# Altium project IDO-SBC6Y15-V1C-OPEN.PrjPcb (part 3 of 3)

## Sheet P12 EXPAND.SchDoc
size 594 x 420 mm
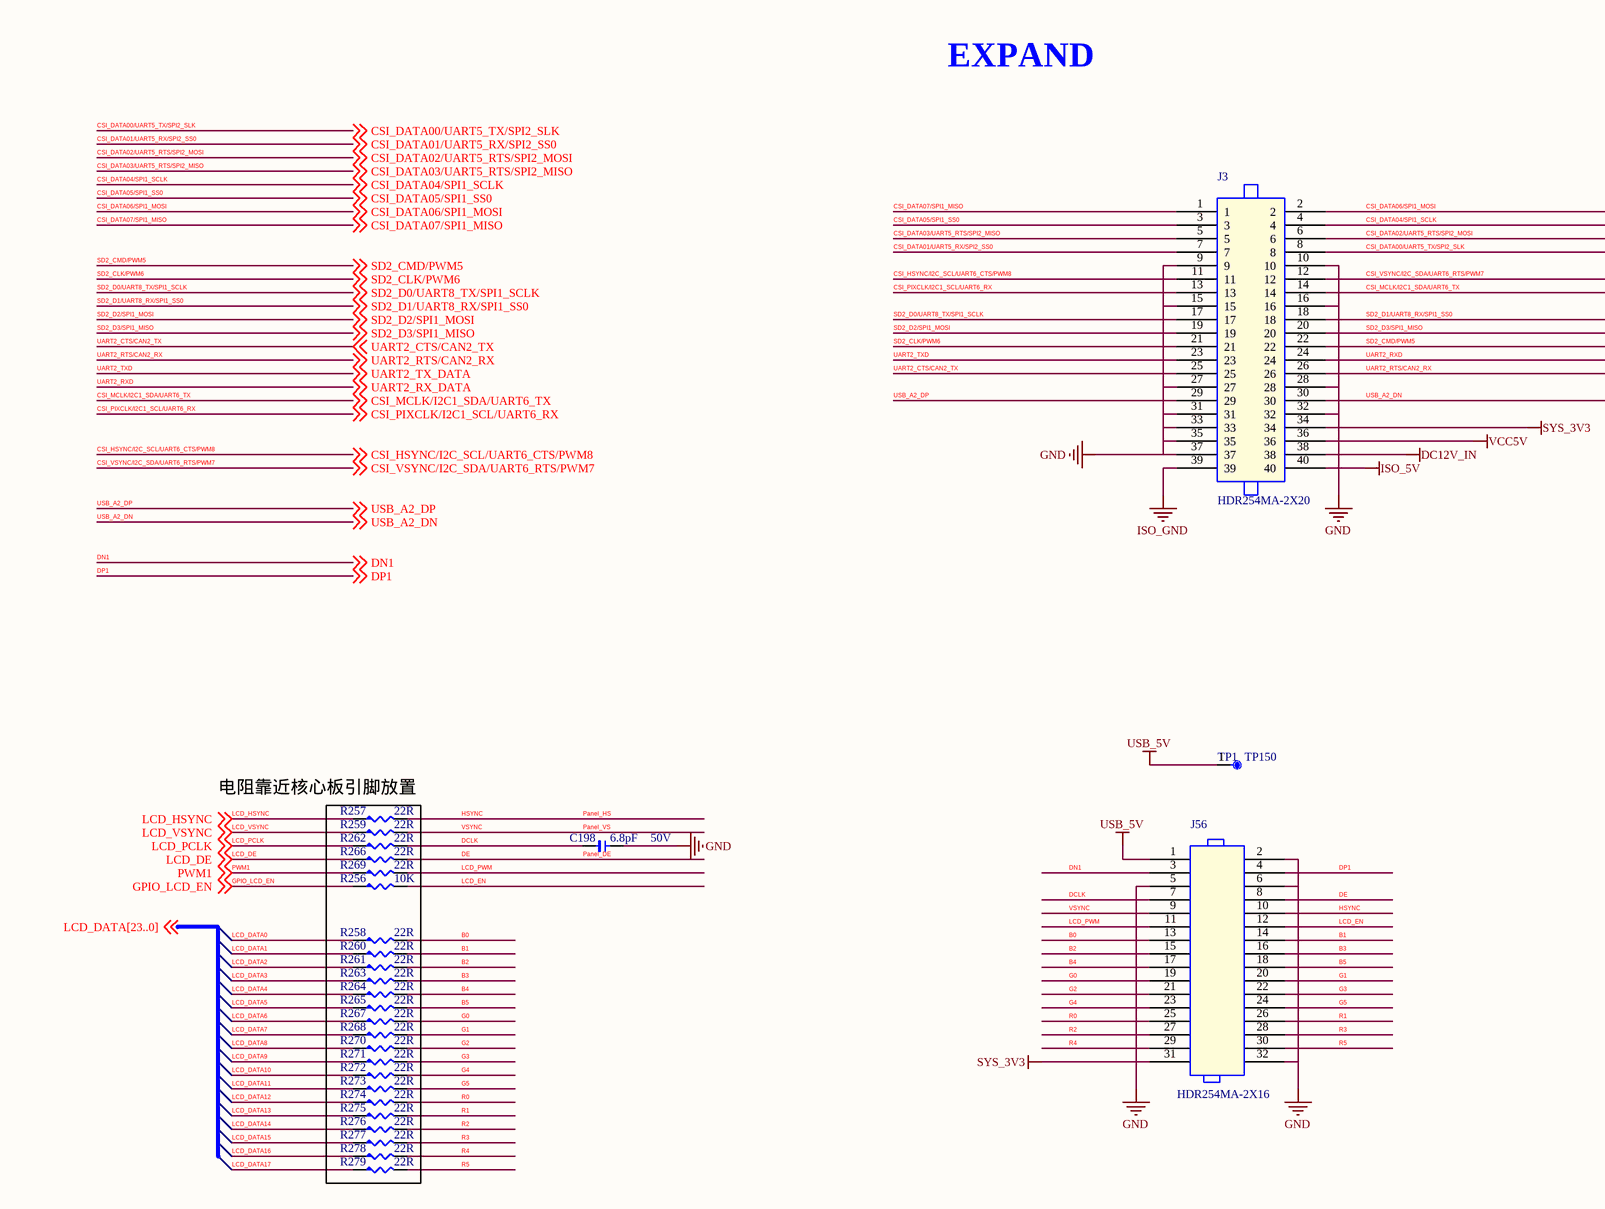
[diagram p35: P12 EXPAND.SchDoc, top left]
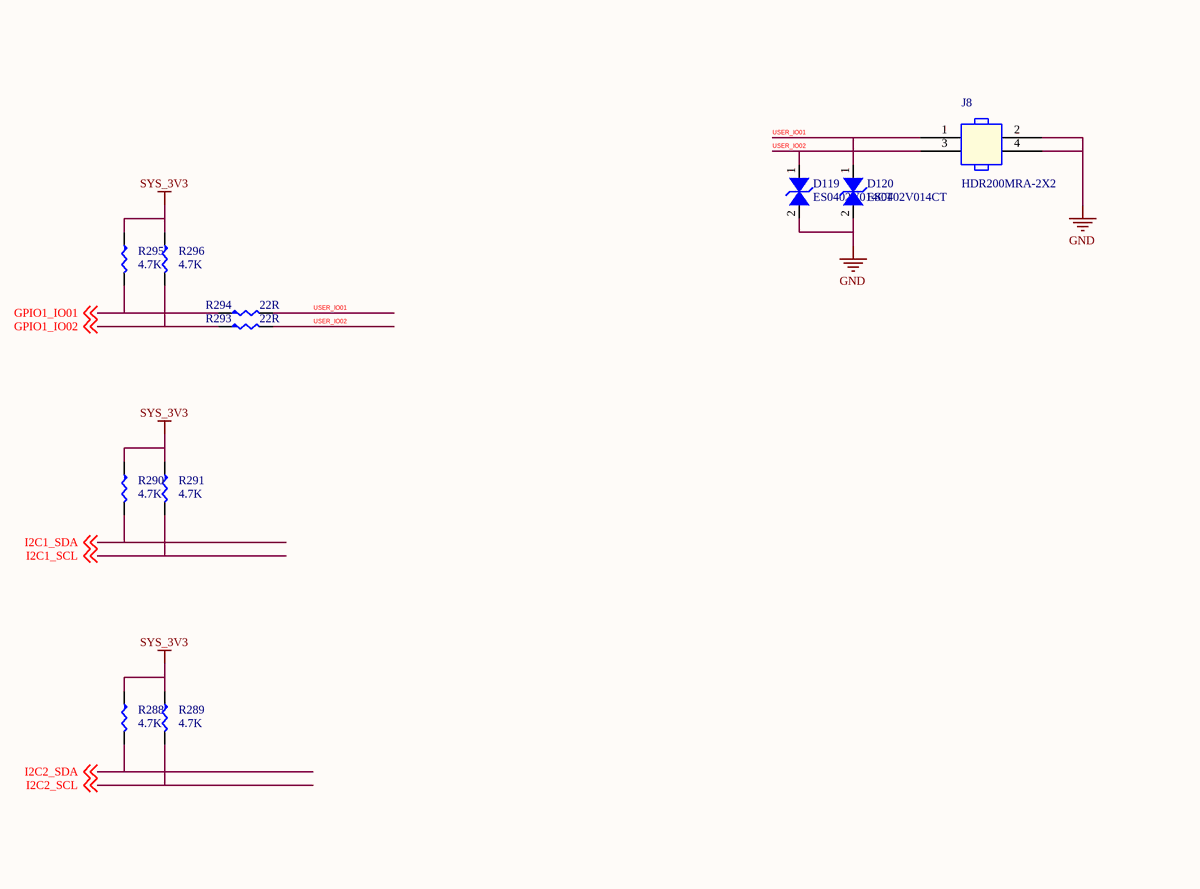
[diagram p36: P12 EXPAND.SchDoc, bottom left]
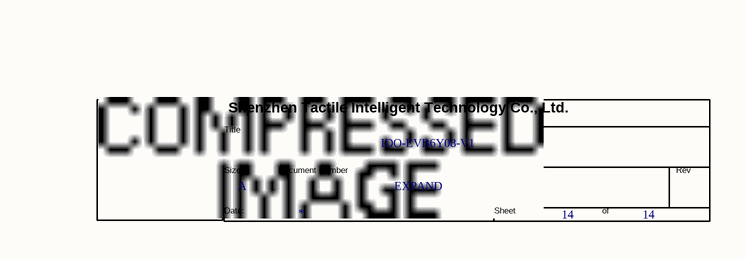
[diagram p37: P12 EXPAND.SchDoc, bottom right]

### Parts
(Parts that share a designator on the sheet are numbered #1, #2 ... from top to bottom, then left to right.)
*#11  Doc: EXPAND  Title: IDO-EVB6Y08-V1  Page Size: A  Page Number: 14  (hidden comment: TitleBlock1)  (graphical)
C198  6.8pF  DSC2: 50V  [1206]
D119  ES0402V014CT  [V0402]
D120  ES0402V014CT  [V0402]
J3  HDR254MA-2X20  [HDR254MA-2X20]
J8  HDR200MRA-2X2  [HDR200MRA-2X2]
J56  HDR254MA-2X16  [HDR254MA-2X16]
R256  10K  [R0402L]
R257  22R  [R0402L]
R258  22R  [R0402L]
R259  22R  [R0402L]
R260  22R  [R0402L]
R261  22R  [R0402L]
R262  22R  [R0402L]
R263  22R  [R0402L]
R264  22R  [R0402L]
R265  22R  [R0402L]
R266  22R  [R0402L]
R267  22R  [R0402L]
R268  22R  [R0402L]
R269  22R  [R0402L]
R270  22R  [R0402L]
R271  22R  [R0402L]
R272  22R  [R0402L]
R273  22R  [R0402L]
R274  22R  [R0402L]
R275  22R  [R0402L]
R276  22R  [R0402L]
R277  22R  [R0402L]
R278  22R  [R0402L]
R279  22R  [R0402L]
R288  4.7K  [R0402L]
R289  4.7K  [R0402L]
R290  4.7K  [R0402L]
R291  4.7K  [R0402L]
R293  22R  [R0402L]
R294  22R  [R0402L]
R295  4.7K  [R0402L]
R296  4.7K  [R0402L]
TP1  TP150  [smd_tp_1mm]

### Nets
DC12V_IN: J3.38
GND: C198.1 D119.2(I/O1) D120.2(I/O1) J3.9 J3.10 J3.15 J3.16 J3.27 J3.28 J3.31 J3.32 J3.33 J3.35 J3.37 J8.2 J8.4 J56.2 J56.5 J56.6 J56.32
ISO_5V: J3.40
ISO_GND: J3.39
SYS_3V3: J3.34 J56.31 R288.1 R289.1 R290.1 R291.1 R295.1 R296.1
USB_5V: J56.1 TP1.1
VCC5V: J3.36
B0: J56.13 R258.2
B1: J56.14 R260.2
B2: J56.15 R261.2
B3: J56.16 R263.2
B4: J56.17 R264.2
B5: J56.18 R265.2
CSI_DATA00/UART5_TX/SPI2_SLK: J3.8 ; off-sheet CSI_DATA00/UART5_TX/SPI2_SLK
CSI_DATA01/UART5_RX/SPI2_SS0: J3.7 ; off-sheet CSI_DATA01/UART5_RX/SPI2_SS0
CSI_DATA02/UART5_RTS/SPI2_MOSI: J3.6 ; off-sheet CSI_DATA02/UART5_RTS/SPI2_MOSI
CSI_DATA03/UART5_RTS/SPI2_MISO: J3.5 ; off-sheet CSI_DATA03/UART5_RTS/SPI2_MISO
CSI_DATA04/SPI1_SCLK: J3.4 ; off-sheet CSI_DATA04/SPI1_SCLK
CSI_DATA05/SPI1_SS0: J3.3 ; off-sheet CSI_DATA05/SPI1_SS0
CSI_DATA06/SPI1_MOSI: J3.2 ; off-sheet CSI_DATA06/SPI1_MOSI
CSI_DATA07/SPI1_MISO: J3.1 ; off-sheet CSI_DATA07/SPI1_MISO
CSI_HSYNC/I2C_SCL/UART6_CTS/PWM8: J3.11 ; off-sheet CSI_HSYNC/I2C_SCL/UART6_CTS/PWM8
CSI_MCLK/I2C1_SDA/UART6_TX: J3.14 ; off-sheet CSI_MCLK/I2C1_SDA/UART6_TX
CSI_PIXCLK/I2C1_SCL/UART6_RX: J3.13 ; off-sheet CSI_PIXCLK/I2C1_SCL/UART6_RX
CSI_VSYNC/I2C_SDA/UART6_RTS/PWM7: J3.12 ; off-sheet CSI_VSYNC/I2C_SDA/UART6_RTS/PWM7
DCLK: C198.2 J56.7 R262.2
DE: J56.8 R266.2  [also labelled Panel_DE]
DN1: J56.3 ; off-sheet DN1
DP1: J56.4 ; off-sheet DP1
G0: J56.19 R267.2
G1: J56.20 R268.2
G2: J56.21 R270.2
G3: J56.22 R271.2
G4: J56.23 R272.2
G5: J56.24 R273.2
GPIO1_IO01: R294.1 R295.2 ; off-sheet GPIO1_IO01
GPIO1_IO02: R293.1 R296.2 ; off-sheet GPIO1_IO02
GPIO_LCD_EN: R256.1 ; off-sheet GPIO_LCD_EN
HSYNC: J56.10 R257.2  [also labelled Panel_HS]
I2C1_SCL: R291.2 ; off-sheet I2C1_SCL  [project net CSI_PIXCLK]
I2C1_SDA: R290.2 ; off-sheet I2C1_SDA  [project net CSI_MCLK]
I2C2_SCL: R289.2 ; off-sheet I2C2_SCL  [project net CSI_HSYNC]
I2C2_SDA: R288.2 ; off-sheet I2C2_SDA  [project net CSI_VSYNC]
LCD_DATA0: R258.1
LCD_DATA1: R260.1
LCD_DATA2: R261.1
LCD_DATA3: R263.1
LCD_DATA4: R264.1
LCD_DATA5: R265.1
LCD_DATA6: R267.1
LCD_DATA7: R268.1
LCD_DATA8: R270.1
LCD_DATA9: R271.1
LCD_DATA10: R272.1
LCD_DATA11: R273.1
LCD_DATA12: R274.1
LCD_DATA13: R275.1
LCD_DATA14: R276.1
LCD_DATA15: R277.1
LCD_DATA16: R278.1
LCD_DATA17: R279.1
LCD_DE: R266.1 ; off-sheet LCD_DE
LCD_EN: J56.12 R256.2
LCD_HSYNC: R257.1 ; off-sheet LCD_HSYNC
LCD_PCLK: R262.1 ; off-sheet LCD_PCLK
LCD_PWM: J56.11 R269.2
LCD_VSYNC: R259.1 ; off-sheet LCD_VSYNC
Panel_VS: J56.9 R259.2  [also labelled VSYNC]
PWM1: R269.1 ; off-sheet PWM1  [project net GPIO1_IO08]
R0: J56.25 R274.2
R1: J56.26 R275.2
R2: J56.27 R276.2
R3: J56.28 R277.2
R4: J56.29 R278.2
R5: J56.30 R279.2
SD2_CLK/PWM6: J3.21 ; off-sheet SD2_CLK/PWM6
SD2_CMD/PWM5: J3.22 ; off-sheet SD2_CMD/PWM5
SD2_D0/UART8_TX/SPI1_SCLK: J3.17 ; off-sheet SD2_D0/UART8_TX/SPI1_SCLK
SD2_D1/UART8_RX/SPI1_SS0: J3.18 ; off-sheet SD2_D1/UART8_RX/SPI1_SS0
SD2_D2/SPI1_MOSI: J3.19 ; off-sheet SD2_D2/SPI1_MOSI
SD2_D3/SPI1_MISO: J3.20 ; off-sheet SD2_D3/SPI1_MISO
UART2_CTS/CAN2_TX: J3.25 ; off-sheet UART2_CTS/CAN2_TX
UART2_RTS/CAN2_RX: J3.26 ; off-sheet UART2_RTS/CAN2_RX
UART2_RX_DATA: J3.24 ; off-sheet UART2_RX_DATA  [also labelled UART2_RXD]
UART2_TX_DATA: J3.23 ; off-sheet UART2_TX_DATA  [also labelled UART2_TXD]
USB_A2_DN: J3.30 ; off-sheet USB_A2_DN
USB_A2_DP: J3.29 ; off-sheet USB_A2_DP
USER_IO01: D120.1(I/O2) J8.1 R294.2
USER_IO02: D119.1(I/O2) J8.3 R293.2

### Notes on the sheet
- EXPAND
- 电阻靠近核心板引脚放置

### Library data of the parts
C198 = C-0402: Part Number: C020102120018; Part Name: 贴片电容; Manufacture: 三星¦国巨¦村田; ERP Number: 1010200056; DSC1: ±0.25PF; DSC3: C0G; ID: 18; PCB Footprint: C0402L
D119 D120 = DI-ESD: ESD 0402; Part Number: C040502250002; Manufacture P/N: MLVG04021R0UV18; Manufacturer: INPAQ; Manufacture: AEM; PN Type: Varistor; ERP Number: 1010800023; DSC1: 双向; DSC2: Vdc=14V; DSC3: Vbr=300V; DSC4: Vc=30V; DSC5: Cj=0.25pF; ID: 2
J3 = J-HDR-D-40: Part Number: J010104013835; Part Name: 双排针; DSC1: 双排单塑; DSC2: 2x20; DSC3: 2.54mm脚距; DSC4: 通孔直针; DSC5: 针长11.5mm 3+2.5(H塑高)+6mm; DSC6: 黑胶; DSC7: A2541WV-2x20P(CJT); ID: 64
J8 = J-HDR-D-4: Part Name: 双排针; Part Number: J010102760077; ID: 21; DSC7: A2005WR-2x2P（CJT); DSC6: 黑胶; DSC5: 2.8+2(H塑高)+4 mm; DSC4: 通孔弯针; DSC3: 2mm脚距; DSC2: 2x2; DSC1: 双排单塑; ERP Number: 1040100150
J56 = J-HDR-D-30_1: Part Name: 双排针; Part Number: J010102760129; ID: 52; DSC7: A2541WV-2x16P(CJT); DSC6: 黑胶; DSC5: 针长11.5mm 3+2.5(H塑高)+6mm; DSC4: 通孔直针; DSC3: 2.54mm脚距; DSC2: 2x16; DSC1: 双排单塑
R256 = R-0402: Part Name: 贴片电阻; Part Number: C011002080856; ERP Number: 1010200140; DSC1: ±1%; DSC2: 1/16W; ID: 856
R257 R259 R262 R266 R269 = R-0402: Part Name: 贴片电阻; Part Number: C011002080552; DSC1: ±1%; DSC2: 1/16W; ID: 552
R258 R260 R261 R263-R265 R267 R268 R270-R279 R293 R294 = R-0402: Part Number: C011002080552; Part Name: 贴片电阻; ID: 552; DSC2: 1/16W; DSC1: ±1%
R288 R291 R296 = R-0402: Part Number: C011002080818; Part Name: 贴片电阻; ID: 818; DSC2: 1/16W; DSC1: ±1%; ERP Number: 1010200445
R289 R290 R295 = R-0402: Part Name: 贴片电阻; Part Number: C011002080818; ERP Number: 1010200445; DSC1: ±1%; DSC2: 1/16W; ID: 818
TP1 = TP-TEST: Part Number: CAD; Part Name: 测试点; ID: 5; DSC4: 单面; DSC3: 圆形; DSC2: 无孔; DSC1: 焊盘1.5mm

## Sheet P11 4G_WIFI.SchDoc
size 594 x 420 mm
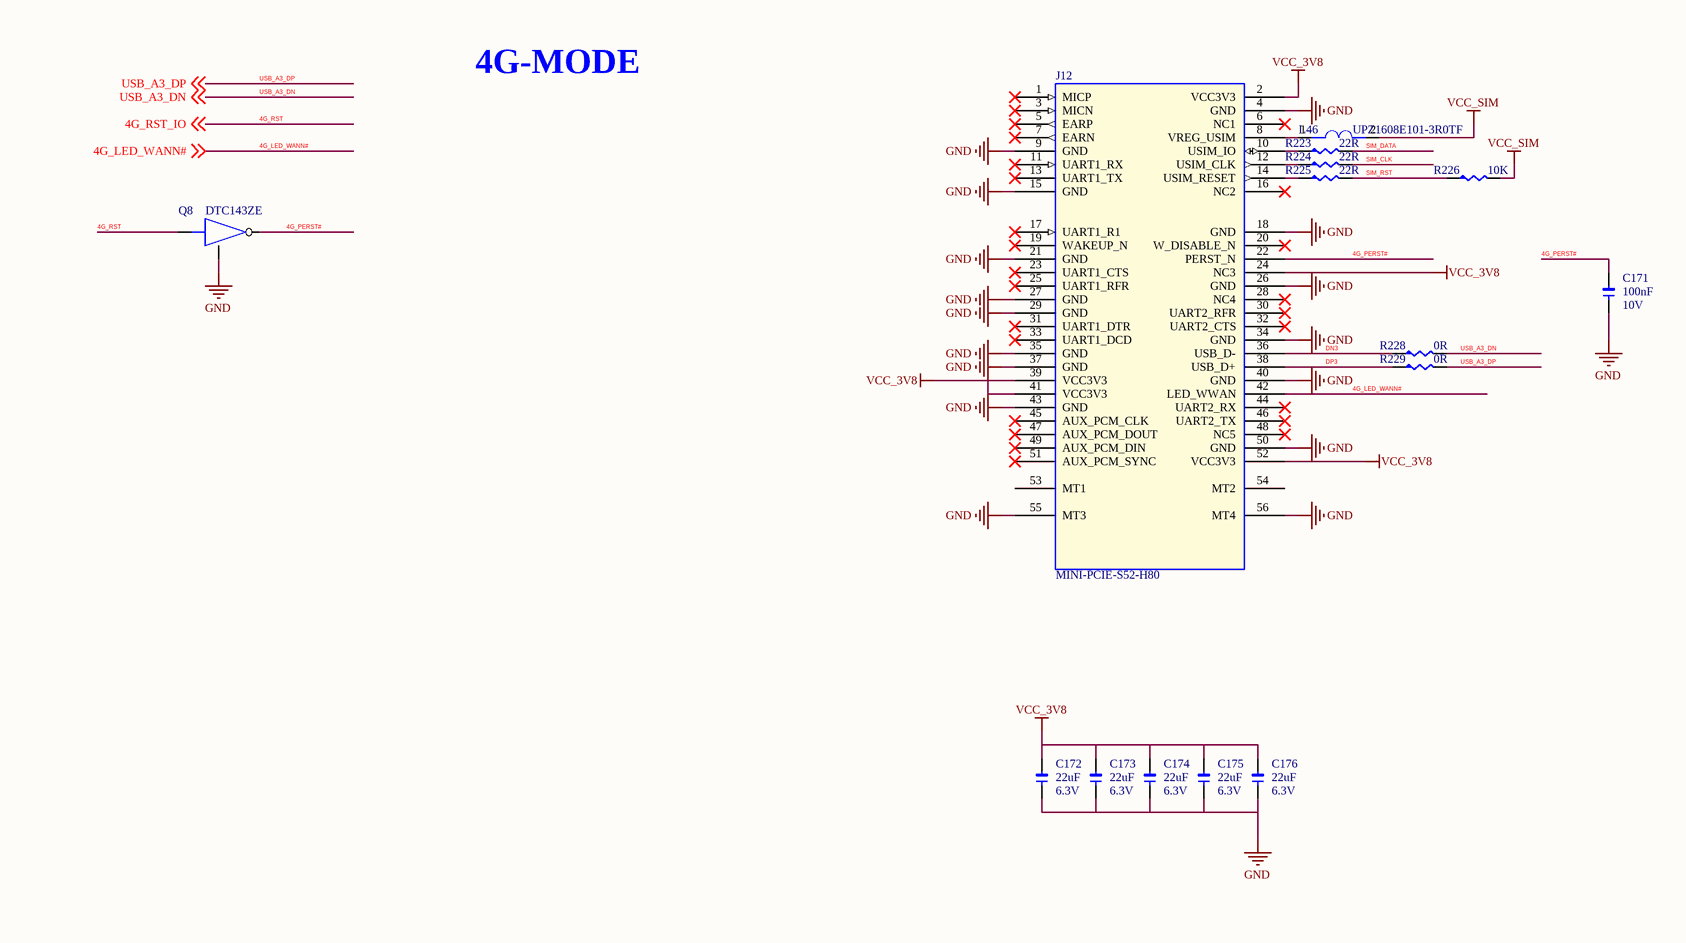
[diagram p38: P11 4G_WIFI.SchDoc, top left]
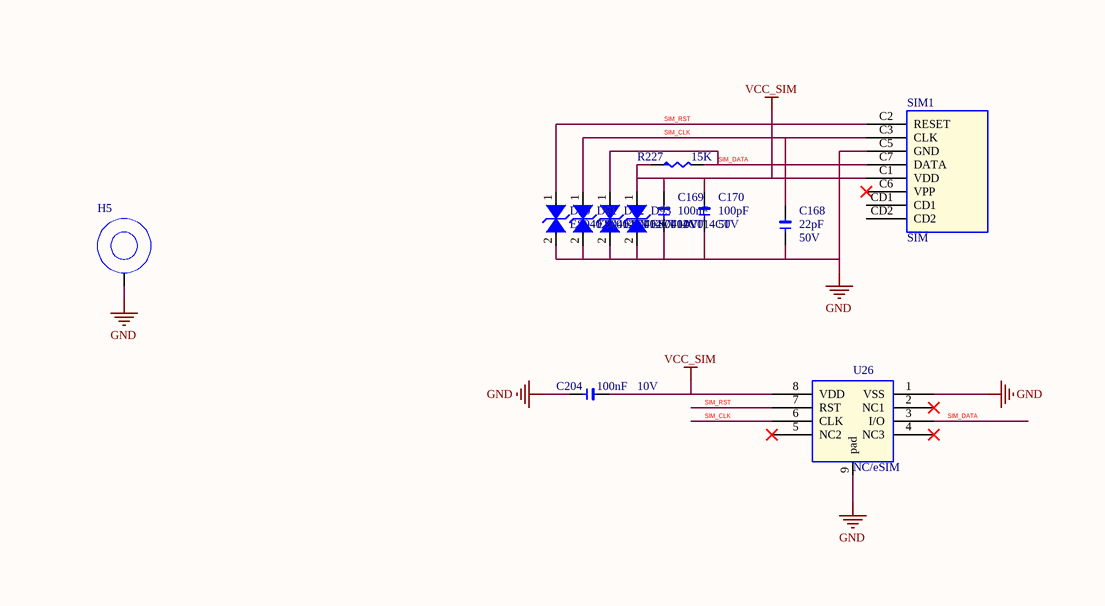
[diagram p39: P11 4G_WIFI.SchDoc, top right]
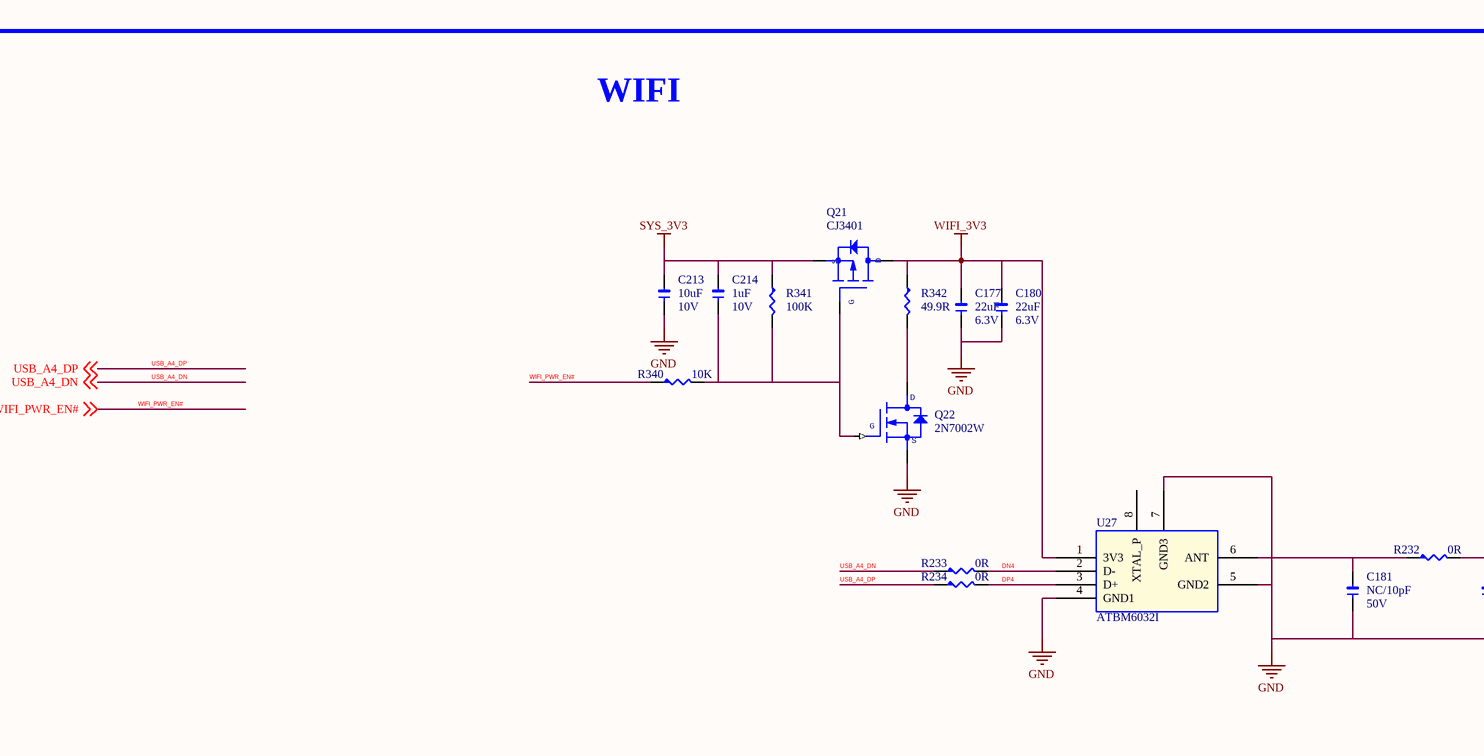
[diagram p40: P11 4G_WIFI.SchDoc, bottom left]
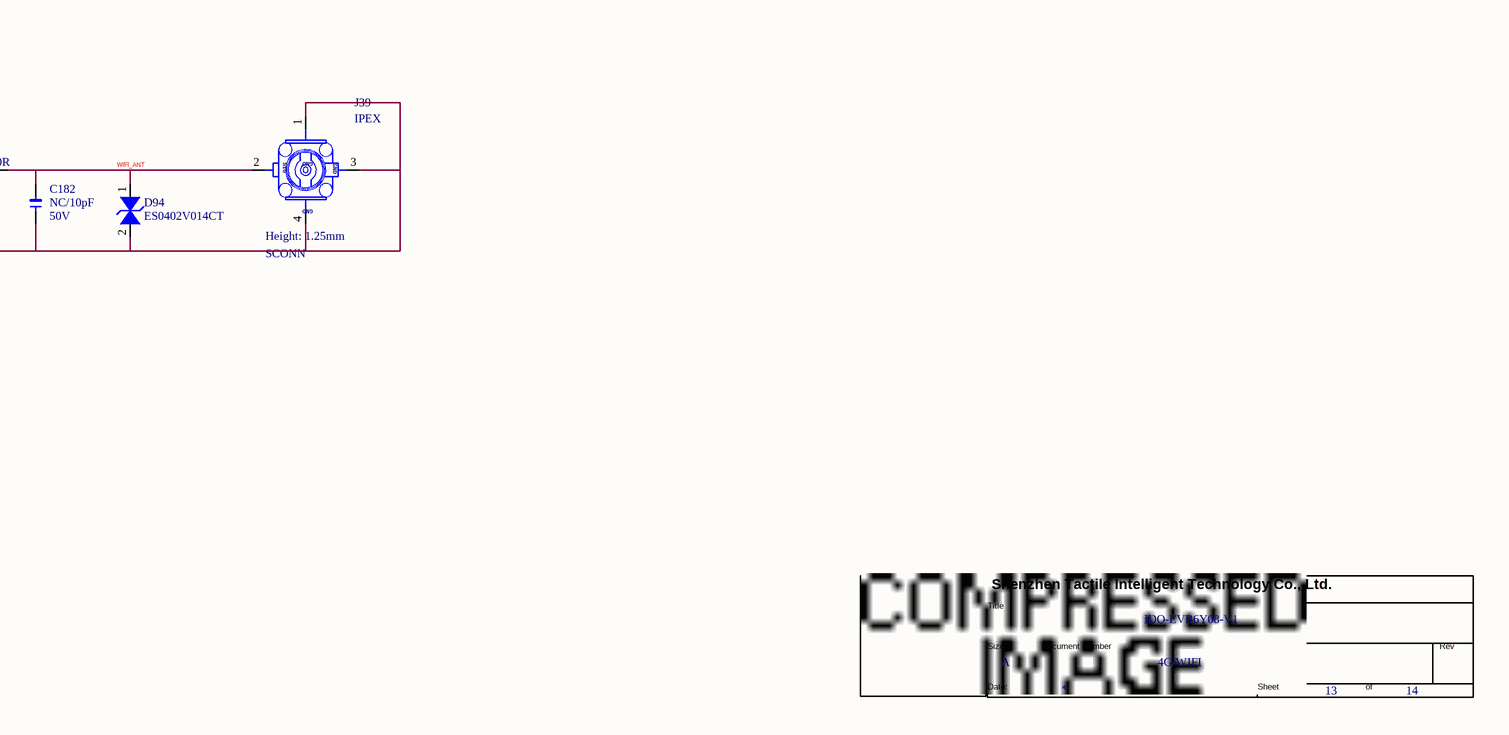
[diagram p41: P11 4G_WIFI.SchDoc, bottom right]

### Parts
(Parts that share a designator on the sheet are numbered #1, #2 ... from top to bottom, then left to right.)
*#12  Doc: 4G/WIFI  Title: IDO-EVB6Y08-V1  Page Size: A  Page Number: 13  Page Count: 14  (hidden comment: TitleBlock1)  (graphical)
C168  22pF  DSC2: 50V  [1206]
C169  100nF  DSC2: 10V  [1206]
C170  100pF  DSC2: 50V  [1206]
C171  100nF  DSC2: 10V  [1206]
C172  22uF  DSC2: 6.3V  [1206]
C173  22uF  DSC2: 6.3V  [1206]
C174  22uF  DSC2: 6.3V  [1206]
C175  22uF  DSC2: 6.3V  [1206]
C176  22uF  DSC2: 6.3V  [1206]
C177  22uF  DSC2: 6.3V  [1206]
C180  22uF  DSC2: 6.3V  [1206]
C181  NC/10pF  DSC2: 50V  [1206]
C182  NC/10pF  DSC2: 50V  [1206]
C204  100nF  DSC2: 10V  [1206]
C213  10uF  DSC2: 10V  [1206]
C214  1uF  DSC2: 10V  [1206]
D90  ES0402V014CT  [V0402]
D91  ES0402V014CT  [V0402]
D92  ES0402V014CT  [V0402]
D93  ES0402V014CT  [V0402]
D94  ES0402V014CT  [V0402]
H5  HOLE  [mtg250_600]  (value not drawn)
J12  MINI-PCIE-S52-H80  [M_MINIPCIE_SOCKET_CK]
J39  IPEX  Material: SCONN  Height: 1.25mm  [IPEX-20279-001E]
L46  UPZ1608E101-3R0TF  [L0603]
Q8  DTC143ZE  [SOT523]
Q21  CJ3401  [SOT23]
Q22  2N7002W  [SOT323]
R223  22R  [R0402L]
R224  22R  [R0402L]
R225  22R  [R0402L]
R226  10K  [R0402L]
R227  15K  [R0402L]
R228  0R  [R0402L]
R229  0R  [R0402L]
R232  0R  [R0402L]
R233  0R  [R0402L]
R234  0R  [R0402L]
R340  10K  [R0402L]
R341  100K  [R0402L]
R342  49.9R  [R0402L]
SIM1  SIM  [SIM-91288-021]
U26  NC/eSIM  [eSIM]
U27  ATBM6032I  [ATBM6032I]

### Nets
GND: C168.1 C169.1 C170.1 C171.1 C172.1 C173.1 C174.1 C175.1 C176.1 C177.1 C180.1 C181.1 C182.1 C204.1 C213.1 D90.2(I/O1) D91.2(I/O1) D92.2(I/O1) D93.2(I/O1) D94.2(I/O1) H5.1 J12.4(GND) J12.9(GND) J12.15(GND) J12.18(GND) J12.21(GND) J12.26(GND) J12.27(GND) J12.29(GND) J12.34(GND) J12.35(GND) J12.37(GND) J12.40(GND) J12.43(GND) J12.50(GND) J12.55(MT3) J12.56(MT4) J39.1(GND1) J39.3(GND2) J39.4(GND3) Q8.2 Q22.2(SOURCE) SIM1.C5(GND) U26.1(VSS) U26.9(pad) U27.4(GND1) U27.5(GND2) U27.7(GND3)
SYS_3V3: C213.2 C214.2 Q21.2(SOURCE) R341.1
VCC_3V8: C172.2 C173.2 C174.2 C175.2 C176.2 J12.2(VCC3V3) J12.24(NC3) J12.39(VCC3V3) J12.41(VCC3V3) J12.52(VCC3V3)
VCC_SIM: C169.2 C170.2 C204.2 D93.1(I/O2) L46.2 R226.2 R227.1 SIM1.C1(VDD) U26.8(VDD)
WIFI_3V3: C177.2 C180.2 Q21.3(DRAIN) R342.1 U27.1(3V3)
4G_LED_WANN#: J12.42(LED_WWAN) ; off-sheet 4G_LED_WANN#
4G_PERST#: C171.2 J12.22(PERST_N) Q8.3
4G_RST: Q8.1 ; off-sheet 4G_RST_IO  [also labelled 4G_RST_IO]
DN3: J12.36(USB_D-) R228.1
DN4: R233.2 U27.2(D-)
DP3: J12.38(USB_D+) R229.1
DP4: R234.2 U27.3(D+)
SIM_CLK: C168.2 D91.1(I/O2) R224.2 SIM1.C3(CLK) U26.6(CLK)
SIM_DATA: D92.1(I/O2) R223.2 R227.2 SIM1.C7(DATA) U26.3(I/O)
SIM_RST: D90.1(I/O2) R225.2 R226.1 SIM1.C2(RESET) U26.7(RST)
USB_A3_DN: R228.2 ; off-sheet USB_A3_DN
USB_A3_DP: R229.2 ; off-sheet USB_A3_DP
USB_A4_DN: R233.1 ; off-sheet USB_A4_DN
USB_A4_DP: R234.1 ; off-sheet USB_A4_DP
WIFI_ANT: C182.2 D94.1(I/O2) J39.2(SIG) R232.2
WIFI_PWR_EN#: R340.1 ; off-sheet WIFI_PWR_EN#  [project net SNVS_TAMPER9]
NetC181_2: C181.2 R232.1 U27.6(ANT)
NetC214_1: C214.1 Q21.1(GATE) Q22.1(GATE) R340.2 R341.2
NetJ12_8: J12.8(VREG_USIM) L46.1
NetJ12_10: J12.10(USIM_IO) R223.1
NetJ12_12: J12.12(USIM_CLK) R224.1
NetJ12_14: J12.14(USIM_RESET) R225.1
NetQ22_3: Q22.3(DRAIN) R342.2

Not connected (* = marked no-connect by the designer): J12 1(MICP)* 3(MICN)* 5(EARP)* 6(NC1)* 7(EARN)* 11(UART1_RX)* 13(UART1_TX)* 16(NC2)* 17(UART1_R1)* 19(WAKEUP_N)* 20(W_DISABLE_N)* 23(UART1_CTS)* 25(UART1_RFR)* 28(NC4)* 30(UART2_RFR)* 31(UART1_DTR)* 32(UART2_CTS)* 33(UART1_DCD)* 44(UART2_RX)* 45(AUX_PCM_CLK)* 46(UART2_TX)* 47(AUX_PCM_DOUT)* 48(NC5)* 49(AUX_PCM_DIN)* 51(AUX_PCM_SYNC)* 53(MT1) 54(MT2); SIM1 C6(VPP)* CD1 CD2; U26 2(NC1)* 4(NC3)* 5(NC2)*; U27 8(XTAL_P)

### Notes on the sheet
- 4G-MODE
- WIFI

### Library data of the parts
C168 = C-0402: Manufacture: 三星¦国巨¦村田; Part Name: 贴片电容; Part Number: C020102120029; PCB Footprint: C0402L; ID: 29; DSC3: C0G; DSC1: ±5%; ERP Number: 1010200272
C169 C204 = C-0402: Part Number: C020102120060; Part Name: 贴片电容; Manufacture: 三星¦国巨¦村田; PCB Footprint: C0402L; DSC1: ±10%; DSC3: X7R; ID: 60
C170 = C-0402: Manufacture: 三星¦国巨¦村田; Part Name: 贴片电容; Part Number: C020102120040; PCB Footprint: C0402L; ID: 40; DSC3: C0G; DSC1: ±5%; ERP Number: 1010200152
C171 = C-0402: Manufacture: 三星¦国巨¦村田; Part Name: 贴片电容; Part Number: C020102120060; PCB Footprint: C0402L; ID: 60; DSC3: X7R; DSC1: ±10%
C172-C176 = C-0603: Manufacture: 三星¦国巨¦村田; Part Name: 贴片电容; Part Number: C020102120072; PCB Footprint: C0603L; ID: 72; DSC3: X5R; DSC1: ±20%; ERP Number: 1010200133
C177 C180 = C-0603: Manufacture: 三星¦国巨¦村田; Part Name: 贴片电容; Part Number: C020102120072; ID: 72; DSC3: X5R; DSC1: ±20%; ERP Number: 1010200133; PCB Footprint: C0603L
C181 C182 = C-0402: Manufacture: 三星¦国巨¦村田; Part Name: 贴片电容; Part Number: C020102120021; ID: 21; DSC3: C0G; DSC1: ±5%; ERP Number: 1010200151; PCB Footprint: C0402L
C213 = C-0603: Manufacture: 三星¦国巨¦村田; Part Name: 贴片电容; Part Number: C020102120071; ID: 71; DSC3: X5R; DSC1: ±20%; ERP Number: 1010200076; PCB Footprint: C0603L
C214 = C-0402: Manufacture: 三星¦国巨¦村田; Part Name: 贴片电容; Part Number: C020102120064; ID: 64; DSC3: X5R; DSC1: ±10%; ERP Number: 1010200054; PCB Footprint: C0402L
D90-D94 = DI-ESD: ESD 0402; Part Number: C040502250002; Manufacture P/N: MLVG04021R0UV18; Manufacturer: INPAQ; Manufacture: AEM; PN Type: Varistor; ID: 2; DSC5: Cj=0.25pF; DSC4: Vc=30V; DSC3: Vbr=300V; DSC2: Vdc=14V; DSC1: 双向; ERP Number: 1010800023
J12 = J-MINIPCIE-52P_0: Part Number: J050102900003; Part Name: 金手指连接器; CLASS: IO; DSC1: miniPCIE座子 H=8.0mm; DSC2: 52P; DSC3: 贴片; DSC4: 91304-80-052R2(UMaxconn); ID: 3
J39 = RF-IPEX-20279: SMD micro Coaxial Connector Receptacle vertial; Part Number: J110103040001; Part Name: IPEX座; Pack_Type: MHF-20279; DSC1: IPEX-20279-001E-01 板端贴片天线座 U.LF接头; DSC2: 贴片; ID: 1
L46 = FB-0603: SMD Multilayer Ferrite Chip Bead,3A,30Ohm,0.03R; Manufacturer: SUNLORD; Manufacture2 P/N: PBY160808T-400Y-N; Manufacture P/N: PZ1608D300-3R0TF; Part Number: C060502370005; Manufacture: 顺络; Part Name: 贴片磁珠; PN Type: SMD FERRITE BEAD; ID: 5; DSC4: 电源线; DSC3: DCR=30mΩ; DSC1: 100Ω@100MHz; ERP Number: 1010200207
Q8 = S-NPN: Part Number: C030302200002; Part Name: 数字三极管; Manufacture: 长电; ERP Number: 1010800049; DSC1: NPN; DSC2: Ic=100mA; DSC3: Vce=50V; DSC4: 150mW; ID: 2
Q21 = P-MOS: Manufacture: 长电; Part Number: C030202190001; ID: 1; DSC5: pd=350mW; DSC4: Vgs=±12V; DSC3: Vgs(th)=1.3V; DSC2: Id=-4.2A; DSC1: Vds=-30V; ERP Number: 1010800001
Q22 = N-MOS: Manufacture: 长电; Part Number: C030202190006; ID: 6; DSC5: pd=200mW; DSC4: Vgs=±20V; DSC3: Vgs(th)=2.5V; DSC2: Id=115mA; DSC1: Vds=60V; ERP Number: 1010800035
R223-R225 = R-0402: as R258 on sheet P12 EXPAND
R226 = R-0402: Part Number: C011002080856; Part Name: 贴片电阻; ID: 856; DSC2: 1/16W; DSC1: ±1%; ERP Number: 1010200140
R227 = R-0402: Part Number: C011002080875; Part Name: 贴片电阻; ID: 875; DSC2: 1/16W; DSC1: ±1%; ERP Number: 1010200458
R228 R229 R233 R234 = R-0402: Part Number: C011002080413; Part Name: 贴片电阻; ID: 413; DSC2: 1/16W; DSC1: ±1%
R232 = R-0402: Part Name: 贴片电阻; Part Number: C011002080413; DSC1: ±1%; DSC2: 1/16W; ID: 413
R340 = R-0402: as R256 on sheet P12 EXPAND
R341 = R-0402: Part Number: C011002080976; Part Name: 贴片电阻; ID: 976; DSC2: 1/16W; DSC1: ±1%; ERP Number: 1010200137
R342 = R-0402: Part Number: C011002080595; Part Name: 贴片电阻; ID: 595; DSC2: 1/16W; DSC1: ±1%; ERP Number: 1010200099
SIM1 = J-SIM-021_0: Part Name: SIM卡座; Part Number: J080202990002; ID: 5; DSC4: SIM-021(硕方); DSC3: 贴片; DSC2: 31.0*25.1*26mm; DSC1: SIM卡座 91228 抽屉式 8P; ERP Number: 1040100109
U26 = eSIM
U27 = M-ATBM6032I_0: Manufacture: 高拓讯达; Part Name: 无线模块; Part Number: C230404233852; ID: 4; DSC4: 2.412-2.484GHz; DSC3: IEEE 802.11b/g/n 1T1R; DSC1: L13.00*W12.20*H2.00mm

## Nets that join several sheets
DC12V_IN: P05 POWER_SUPPLY_LED (8 pins), P12 EXPAND (J3.38)
GND: P05 POWER_SUPPLY_LED (51 pins), P06 SOM6ULX (18 pins), P07 SD_RTC (20 pins), P08 USB (37 pins), P09 ETHERNET (23 pins), P10 UART_Debug (16 pins), P12 EXPAND (20 pins), P11 4G_WIFI (48 pins)
GND_EARTH: P05 POWER_SUPPLY_LED (6 pins), P08 USB (J7.5 J7.6 J7.7), P09 ETHERNET (12 pins), P10 UART_Debug (D101.2 D102.2 D103.2 D105.2)
ISO_5V: P10 UART_Debug (20 pins), P12 EXPAND (J3.40)
ISO_GND: P10 UART_Debug (41 pins), P12 EXPAND (J3.39)
SYS_3V3: P05 POWER_SUPPLY_LED (13 pins), P06 SOM6ULX (L7.1), P07 SD_RTC (5 pins), P08 USB (14 pins), P09 ETHERNET (9 pins), P10 UART_Debug (14 pins), P12 EXPAND (8 pins), P11 4G_WIFI (C213.2 C214.2 Q21.2 R341.1)
USB_5V: P08 USB (C55.2 U32.1), P12 EXPAND (J56.1 TP1.1)
USB_OTG1_VBUS: P06 SOM6ULX (C34.2 M1.77), P08 USB (C46.2 D115.1 J7.1 U7.1)
VCC5V: P05 POWER_SUPPLY_LED (7 pins), P06 SOM6ULX (L5.1), P08 USB (C45.2 C211.2 U7.5 U32.5), P10 UART_Debug (C151.2 L36.1), P12 EXPAND (J3.36)
VCC_3V8: P05 POWER_SUPPLY_LED (5 pins), P11 4G_WIFI (10 pins)
VDD_SNVS_3V3: P05 POWER_SUPPLY_LED (7 pins), P06 SOM6ULX (L6.1 R43.1)
4G_LED_WANN#: P05 POWER_SUPPLY_LED (D123.1 LED2.2), P11 4G_WIFI (J12.42)
4G_POWER_EN: P05 POWER_SUPPLY_LED (R23.1), P06 SOM6ULX (M1.57)
4G_RST: P06 SOM6ULX (M1.58), P11 4G_WIFI (Q8.1)
BUZZER_PWM: P05 POWER_SUPPLY_LED (C28.2 Q18.1), P06 SOM6ULX (M1.30)
CAN1_RX: P06 SOM6ULX (M1.108), P10 UART_Debug (R204.2 U21.2)
CAN1_TX: P06 SOM6ULX (M1.107), P10 UART_Debug (U21.3)
CSI_DATA00/UART5_TX/SPI2_SLK: P06 SOM6ULX (R40.2), P12 EXPAND (J3.8)
CSI_DATA01/UART5_RX/SPI2_SS0: P06 SOM6ULX (R41.2), P12 EXPAND (J3.7)
CSI_DATA02/UART5_RTS/SPI2_MOSI: P06 SOM6ULX (R44.2), P12 EXPAND (J3.6)
CSI_DATA03/UART5_RTS/SPI2_MISO: P06 SOM6ULX (R45.2), P12 EXPAND (J3.5)
CSI_DATA04/SPI1_SCLK: P06 SOM6ULX (R46.2), P12 EXPAND (J3.4)
CSI_DATA05/SPI1_SS0: P06 SOM6ULX (R47.2), P12 EXPAND (J3.3)
CSI_DATA06/SPI1_MOSI: P06 SOM6ULX (R48.2), P12 EXPAND (J3.2)
CSI_DATA07/SPI1_MISO: P06 SOM6ULX (R49.2), P12 EXPAND (J3.1)
CSI_HSYNC: P06 SOM6ULX (M1.46 R52.1), P07 SD_RTC (R67.1), P12 EXPAND (R289.2)
CSI_HSYNC/I2C_SCL/UART6_CTS/PWM8: P06 SOM6ULX (R52.2), P12 EXPAND (J3.11)
CSI_MCLK: P06 SOM6ULX (M1.43 R50.1), P12 EXPAND (R290.2)
CSI_MCLK/I2C1_SDA/UART6_TX: P06 SOM6ULX (R50.2), P12 EXPAND (J3.14)
CSI_PIXCLK: P06 SOM6ULX (M1.44 R51.1), P12 EXPAND (R291.2)
CSI_PIXCLK/I2C1_SCL/UART6_RX: P06 SOM6ULX (R51.2), P12 EXPAND (J3.13)
CSI_VSYNC: P06 SOM6ULX (M1.45 R54.1), P07 SD_RTC (R66.1), P12 EXPAND (R288.2)
CSI_VSYNC/I2C_SDA/UART6_RTS/PWM7: P06 SOM6ULX (R54.2), P12 EXPAND (J3.12)
DN1: P08 USB (D19.1 L10.4), P12 EXPAND (J56.3)
DP1: P08 USB (D18.1 L10.3), P12 EXPAND (J56.4)
ENET2_CRS_DV: P06 SOM6ULX (M1.116), P09 ETHERNET (R107.1)
ENET2_nRST: P06 SOM6ULX (M1.88), P09 ETHERNET (R108.1)
ENET2_RXD0: P06 SOM6ULX (M1.119), P09 ETHERNET (R104.1)
ENET2_RXD1: P06 SOM6ULX (M1.118), P09 ETHERNET (R105.1)
ENET2_RXER: P06 SOM6ULX (M1.117), P09 ETHERNET (R106.1)
ENET2_TX_CLK: P06 SOM6ULX (M1.120), P09 ETHERNET (R112.1)
ENET2_TXD0: P06 SOM6ULX (M1.123), P09 ETHERNET (R100.1)
ENET2_TXD1: P06 SOM6ULX (M1.122), P09 ETHERNET (R101.1)
ENET2_TXEN: P06 SOM6ULX (M1.121), P09 ETHERNET (R102.1)
ENET_MDC: P06 SOM6ULX (M1.124), P09 ETHERNET (R99.1)
ENET_MDIO: P06 SOM6ULX (M1.125), P09 ETHERNET (R98.1)
ETH1X_LED1: P06 SOM6ULX (M1.128), P09 ETHERNET (R85.1)
ETH1X_RXN: P06 SOM6ULX (M1.3), P09 ETHERNET (R88.1)
ETH1X_RXP: P06 SOM6ULX (M1.4), P09 ETHERNET (R86.1)
ETH1X_TXN: P06 SOM6ULX (M1.1), P09 ETHERNET (R84.1)
ETH1X_TXP: P06 SOM6ULX (M1.2), P09 ETHERNET (R82.1)
GPIO1_IO00: P06 SOM6ULX (M1.95), P08 USB (R68.1)
GPIO1_IO01: P06 SOM6ULX (M1.94), P12 EXPAND (R294.1 R295.2)
GPIO1_IO02: P06 SOM6ULX (M1.93), P12 EXPAND (R293.1 R296.2)
GPIO1_IO05: P06 SOM6ULX (M1.90), P08 USB (R69.1 U7.4)
GPIO1_IO08: P06 SOM6ULX (M1.89), P12 EXPAND (R269.1)
GPIO-DI: P06 SOM6ULX (M1.62), P10 UART_Debug (R326.2 U28.6)
GPIO_LCD_EN: P06 SOM6ULX (M1.56), P12 EXPAND (R256.1)
IO_KEY: P05 POWER_SUPPLY_LED (R236.1), P06 SOM6ULX (M1.61)
JTAG_MOD: P06 SOM6ULX (M1.87), P10 UART_Debug (R217.1 U29.5)
LCD_DATA0: P06 SOM6ULX (M1.29), P12 EXPAND (R258.1)
LCD_DATA1: P06 SOM6ULX (M1.28), P12 EXPAND (R260.1)
LCD_DATA2: P06 SOM6ULX (M1.27), P12 EXPAND (R261.1)
LCD_DATA3: P06 SOM6ULX (M1.26), P12 EXPAND (R263.1)
LCD_DATA4: P06 SOM6ULX (M1.25), P12 EXPAND (R264.1)
LCD_DATA5: P06 SOM6ULX (M1.24), P12 EXPAND (R265.1)
LCD_DATA6: P06 SOM6ULX (M1.23), P12 EXPAND (R267.1)
LCD_DATA7: P06 SOM6ULX (M1.22), P12 EXPAND (R268.1)
LCD_DATA8: P06 SOM6ULX (M1.21), P12 EXPAND (R270.1)
LCD_DATA9: P06 SOM6ULX (M1.20), P12 EXPAND (R271.1)
LCD_DATA10: P06 SOM6ULX (M1.19), P12 EXPAND (R272.1)
LCD_DATA11: P06 SOM6ULX (M1.18), P12 EXPAND (R273.1)
LCD_DATA12: P06 SOM6ULX (M1.17), P12 EXPAND (R274.1)
LCD_DATA13: P06 SOM6ULX (M1.16), P12 EXPAND (R275.1)
LCD_DATA14: P06 SOM6ULX (M1.15), P12 EXPAND (R276.1)
LCD_DATA15: P06 SOM6ULX (M1.14), P12 EXPAND (R277.1)
LCD_DATA16: P06 SOM6ULX (M1.13), P12 EXPAND (R278.1)
LCD_DATA17: P06 SOM6ULX (M1.12), P12 EXPAND (R279.1)
LCD_DE: P06 SOM6ULX (M1.34), P12 EXPAND (R266.1)
LCD_HSYNC: P06 SOM6ULX (M1.32), P12 EXPAND (R257.1)
LCD_PCLK: P06 SOM6ULX (M1.33), P12 EXPAND (R262.1)
LCD_VSYNC: P06 SOM6ULX (M1.31), P12 EXPAND (R259.1)
PMIC_ON_REQ: P05 POWER_SUPPLY_LED (R10.1), P06 SOM6ULX (M1.66)
POR_B: P06 SOM6ULX (M1.127), P08 USB (R75.1)
RS485_EN_1: P06 SOM6ULX (M1.99), P10 UART_Debug (R213.1 U29.3)
RS485X1_DIN: P06 SOM6ULX (M1.112), P10 UART_Debug (R209.1 U29.2)
RS485X1_DOUT: P06 SOM6ULX (M1.111), P10 UART_Debug (R211.1 U29.6)
RS485X2_DIN: P06 SOM6ULX (M1.113), P10 UART_Debug (R215.1 U29.4)
RS485X2_DOUT: P06 SOM6ULX (M1.114), P10 UART_Debug (R216.1 U29.7)
SD1_CLK: P06 SOM6ULX (M1.36), P07 SD_RTC (R65.1)
SD1_CMD: P06 SOM6ULX (M1.37), P07 SD_RTC (R63.1)
SD1_DATA0: P06 SOM6ULX (M1.41), P07 SD_RTC (R59.1)
SD1_DATA1: P06 SOM6ULX (M1.40), P07 SD_RTC (R60.1)
SD1_DATA2: P06 SOM6ULX (M1.39), P07 SD_RTC (R61.1)
SD1_DATA3: P06 SOM6ULX (M1.38), P07 SD_RTC (R62.1)
SD2_CLK/PWM6: P06 SOM6ULX (R33.2), P12 EXPAND (J3.21)
SD2_CMD/PWM5: P06 SOM6ULX (R32.2), P12 EXPAND (J3.22)
SD2_D0/UART8_TX/SPI1_SCLK: P06 SOM6ULX (R34.2), P12 EXPAND (J3.17)
SD2_D1/UART8_RX/SPI1_SS0: P06 SOM6ULX (R35.2), P12 EXPAND (J3.18)
SD2_D2/SPI1_MOSI: P06 SOM6ULX (R36.2), P12 EXPAND (J3.19)
SD2_D3/SPI1_MISO: P06 SOM6ULX (R37.2), P12 EXPAND (J3.20)
SNVS_TAMPER3: P06 SOM6ULX (M1.59), P09 ETHERNET (R339.1)
SNVS_TAMPER4: P06 SOM6ULX (M1.60), P09 ETHERNET (R338.1)
SNVS_TAMPER7: P05 POWER_SUPPLY_LED (Q23.1 R349.1), P06 SOM6ULX (M1.63)
SNVS_TAMPER8: P06 SOM6ULX (M1.64), P08 USB (R313.1 U32.4)
SNVS_TAMPER9: P06 SOM6ULX (M1.65), P11 4G_WIFI (R340.1)
UART1_RTS: P06 SOM6ULX (M1.100), P07 SD_RTC (R64.1)
UART1_RX_DATA: P06 SOM6ULX (M1.101), P10 UART_Debug (D61.A R243.2)
UART1_TX_DATA: P06 SOM6ULX (M1.102), P10 UART_Debug (R337.1)
UART2_CTS/CAN2_TX: P06 SOM6ULX (R38.2), P12 EXPAND (J3.25)
UART2_RTS/CAN2_RX: P06 SOM6ULX (R39.2), P12 EXPAND (J3.26)
UART2_RX_DATA: P06 SOM6ULX (M1.105), P12 EXPAND (J3.24)
UART2_TX_DATA: P06 SOM6ULX (M1.106), P12 EXPAND (J3.23)
UART3_RX_DATA: P06 SOM6ULX (M1.109), P10 UART_Debug (R203.2 U28.5)
UART3_TX_DATA: P06 SOM6ULX (M1.110), P10 UART_Debug (U28.4)
USB_A2_DN: P08 USB (U8.3), P12 EXPAND (J3.30)
USB_A2_DP: P08 USB (U8.4), P12 EXPAND (J3.29)
USB_A3_DN: P08 USB (U8.6), P11 4G_WIFI (R228.2)
USB_A3_DP: P08 USB (U8.7), P11 4G_WIFI (R229.2)
USB_A4_DN: P08 USB (U8.8), P11 4G_WIFI (R233.1)
USB_A4_DP: P08 USB (U8.9), P11 4G_WIFI (R234.1)
USB_OTG1_DN: P06 SOM6ULX (M1.75), P08 USB (L9.2)
USB_OTG1_DP: P06 SOM6ULX (M1.74), P08 USB (L9.1)
USB_OTG2_DN: P06 SOM6ULX (M1.71), P08 USB (R73.2)
USB_OTG2_DP: P06 SOM6ULX (M1.72), P08 USB (R72.2)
